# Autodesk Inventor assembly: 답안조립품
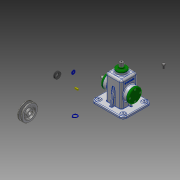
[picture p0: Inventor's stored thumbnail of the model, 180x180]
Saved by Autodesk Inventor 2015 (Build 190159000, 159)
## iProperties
Created: 2016-02
Part Number: 답안조립품
Document SubType Name: Assembly
Designer: Administrator
Author: Administrator
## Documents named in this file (19)
- C:\Users\Administrator\Desktop\460219V1002\답안조립품.iam
- C:\Users\Administrator\Desktop\460219V1002\V-벨트풀리.ipt
- C:\Users\Administrator\Desktop\460219V1002\고정핀.ipt
- C:\Users\Administrator\Desktop\460219V1002\뒤커버.ipt
- C:\Users\Administrator\Desktop\460219V1002\링크.ipt
- C:\Users\Administrator\Desktop\460219V1002\멈춤링 6 x 5.ipt
- C:\Users\Administrator\Desktop\460219V1002\멈춤링 15 x 1.ipt
- C:\Users\Administrator\Desktop\460219V1002\베어링 15 x 35 x 11.ipt
- C:\Users\Administrator\Desktop\460219V1002\본체.ipt
- C:\Users\Administrator\Desktop\460219V1002\볼트 M3 x 8.ipt
- C:\Users\Administrator\Desktop\460219V1002\볼트 M4 x 10.ipt
- C:\Users\Administrator\Desktop\460219V1002\볼트 M6 x 12.ipt
- C:\Users\Administrator\Desktop\460219V1002\상부부시.ipt
- C:\Users\Administrator\Desktop\460219V1002\슬라이드바.ipt
- C:\Users\Administrator\Desktop\460219V1002\앞커버.ipt
- C:\Users\Administrator\Desktop\460219V1002\오일실 15 25 7.ipt
- C:\Users\Administrator\Desktop\460219V1002\와셔.ipt
- C:\Users\Administrator\Desktop\460219V1002\키 5 x 5 x 14.ipt
- C:\Users\Administrator\Desktop\460219V1002\편심축.ipt
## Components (15 placed, 5 different names)
1. V-벨트풀리:1
2. 고정핀:1
3. ISO 4018 M6 x 12:1
4. ISO 4762 M3 x 8:1
5. ISO 4762 M3 x 8:2
6. ISO 4762 M3 x 8:3
7. ISO 4762 M3 x 8:4
8. ISO 4762 M4 x 10:2
9. ISO 4762 M4 x 10:3
10. ISO 4762 M4 x 10:4
11. ISO 4762 M4 x 10:5
12. ISO 4762 M4 x 10:1
13. ISO 4762 M4 x 10:6
14. ISO 4762 M4 x 10:7
15. ISO 4762 M4 x 10:8
